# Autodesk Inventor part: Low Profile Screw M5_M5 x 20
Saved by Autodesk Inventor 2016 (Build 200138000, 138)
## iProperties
Created: 2015-11
Part Number: Low Profile Screw M5_M5 x 20
Material: Generic
Document SubType Name: Modeling
Designer: John
Density: 1 g/cm^3
Appearance: Default
Author: John
Revision Number: ANY
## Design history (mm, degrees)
feature "Cut-Extrude2"
body "Solid1"
